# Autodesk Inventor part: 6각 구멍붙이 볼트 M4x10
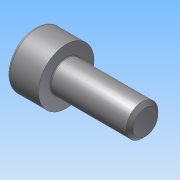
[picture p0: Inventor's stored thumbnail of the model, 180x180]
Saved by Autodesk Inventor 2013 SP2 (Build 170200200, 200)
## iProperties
Created: 2026-07
Part Number: 6각 구멍붙이 볼트 M4x10
Material: Generic
Document SubType Name: Modeling
Designer: a
Density: 1 g/cm^3
Author: a
변환 표준: STEP AP214IS
전처리기: Build: 200, Release: 2013 SP2 Update 6 - Date: Thu 07/17/2014
전송 단위: 밀리미터
불확실성: 0.01
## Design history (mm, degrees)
node "6각 구멍붙이 볼트 M4x101"
body "Solid1"
node "기준1"
